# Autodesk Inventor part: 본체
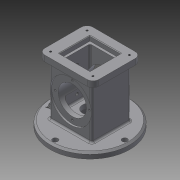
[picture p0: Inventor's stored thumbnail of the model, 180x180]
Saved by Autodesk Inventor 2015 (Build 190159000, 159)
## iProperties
Created: 2019-08
Part Number: 본체
Material: 일반
Document SubType Name: Modeling
Designer: now
Density: 1 g/cm^3
Appearance: 기본값
Author: now
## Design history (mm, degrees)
sketch "스케치1"
  geometry: C1 r 67.5 at (0, 0); 1 further point
  constraints: 1 centre point, 1 coincident
  dimensions: "d0" = 135 diameter of C1
extrude "돌출1" new body sketch "스케치1" distance "d1" = 10; taper "d2" = 0 deg
sketch "스케치2"
  geometry: L1 (-36, 33)-(36, 33); L2 (36, 33)-(36, -33); L3 (36, -33)-(-36, -33); L4 (-36, -33)-(-36, 33); L5 (-36, 33)-(36, -33); L6 (36, 33)-(-36, -33); C1 r 67.5 at (0, 0) reference
  constraints: 12 end point, 2 midpoint, 2 parallel, 1 horizontal, 1 perpendicular
  dimensions: "d3" = 72 distance of L1.start L1.end; "d4" = 66 distance of L3.end L1.start
extrude "돌출2" join sketch "스케치2" distance "d5" = 98; taper "d6" = 0 deg
sketch "스케치4"
  geometry: L1 (-31.5, -10)-(103.5, -10) reference; C1 r 35 at (36, 44); 2 further points
  constraints: 1 centre point, 1 midpoint, 1 vertical alignment
  dimensions: "d8" = 70 diameter of C1; "d9" = 54 distance from line of L1 C1.centre
extrude "돌출3" cut sketch "스케치4" distance "d10" = 3; taper "d11" = 0 deg
sketch "스케치5"
  geometry: C1 r 35 at (0, 0) reference; 1 further point
hole "구멍1" sketch "스케치5" at (0, 0) diameter "d12" = 48; stored, may be unused: countersink angle "d16" = 90 deg, drill point angle "d18" = 118 deg; dims "d13" = 6, "d14" = 4, "d15" = 2, "d17" = 8
fillet "모깎기1" dims "d19" = 3
fillet "모깎기2" dims "d20" = 3
sketch "스케치6"
  geometry: L1 (-46, 41)-(46, 41); L2 (46, 41)-(46, -41); L3 (46, -41)-(-46, -41); L4 (-46, -41)-(-46, 41); L5 (-46, 41)-(46, -41); L6 (46, 41)-(-46, -41); 1 further point
  constraints: 12 end point, 2 midpoint, 2 parallel, 1 horizontal, 1 perpendicular
  dimensions: "d21" = 82 distance of L1.end L2.end; "d22" = 92 distance of L1.start L1.end
extrude "돌출4" join sketch "스케치6" distance "d23" = 10; taper "d24" = 0 deg
fillet "모깎기3" dims "d25" = 10
node "작업 평면2"
sketch "스케치9"
  geometry: 13 further points
  constraints: 4 other
hole "구멍2" sketch "스케치9" at (-36, 31), (-36, -31), (36, -31), (36, 31) diameter "d38" = 3.242; stored, may be unused: countersink angle "d42" = 90 deg, drill point angle "d44" = 118 deg; dims "d39" = 4, "d40" = 4, "d41" = 2, "d43" = 6
sketch "스케치10"
  geometry: C1 r 24 at (0, 0) reference; 2 further points
  constraints: 1 vertical alignment
  dimensions: "d45" = 29 distance of C1.centre point (0, 29)
hole "구멍3" sketch "스케치10" at (0, 29) diameter "d46" = 3.242; stored, may be unused: countersink angle "d50" = 90 deg, drill point angle "d52" = 118 deg; dims "d47" = 4, "d48" = 4, "d49" = 2, "d51" = 6
chamfer "모따기2" distance "d56" = 3; stored, may be unused: second distance "d57" = 2, angle "d58" = 45 deg
sketch "스케치14"
  geometry: C1 r 67.5 at (0, 0) reference; C2 r 25 at (0, 0)
  constraints: 1 centre point, 1 coincident
  dimensions: "d74" = 50 diameter of C2
extrude "돌출9" cut sketch "스케치14" distance "d75" = 18; taper "d76" = 0 deg
fillet "모깎기5" dims "d84" = 3
sketch "스케치17" dims "d96" = 118
  geometry: C1 r 64.5 at (0, 0) reference; 2 further points
  constraints: 2 vertical alignment, 1 coincident, 2 other
hole "구멍7" sketch "스케치17" at (0, 59) diameter "d97" = 9; stored, may be unused: countersink angle "d101" = 90 deg, drill point angle "d103" = 118 deg; dims "d98" = 50, "d99" = 4, "d100" = 2, "d102" = 59.3
sketch "스케치18"
  geometry: C1 r 64.5 at (0, 0) reference; A1 r 59 centre (0, 0) between (0, -59) and (59, 0)
  constraints: 2 point on circle, 1 centre point, 1 coincident, 1 horizontal alignment, 1 vertical alignment
  dimensions: "d107" = 118 diameter of A1
hole "구멍8" sketch "스케치18" at (0, -59), (59, 0) diameter "d108" = 9; stored, may be unused: countersink angle "d112" = 90 deg, drill point angle "d114" = 118 deg; dims "d109" = 50, "d110" = 4, "d111" = 2, "d113" = 59.3
sketch "스케치19"
  geometry: C1 r 64.5 at (0, 0) reference; C2 r 59 at (0, 0)
  constraints: 1 centre point, 1 coincident, 1 other
  dimensions: "d115" = 118 diameter of C2
feature "엠보싱1" sketch "스케치19" dims "d116" = 0.5, "d117" = 0
sketch "스케치20"
  geometry: L1 (-13, 97.5)-(-13, -37.5) reference; 3 further points
  constraints: 2 horizontal alignment
  dimensions: "d132" = 37 distance from line of point (24, 30) L1; "d133" = 43 distance of point (67, 30) point (24, 30)
hole "구멍9" sketch "스케치20" at (67, 30), (24, 30) diameter "d120" = 4.917; stored, may be unused: countersink angle "d124" = 90 deg, drill point angle "d126" = 118 deg; dims "d121" = 12, "d122" = 4, "d123" = 2, "d125" = 35
sketch "스케치21"
  geometry: C1 r 22 at (0, 0) reference; C2 r 12.5 at (0, 0)
  constraints: 1 centre point, 1 coincident
  dimensions: "d129" = 25 diameter of C2
extrude "돌출10" cut sketch "스케치21" stored distance "d130" = 10; taper "d131" = 0 deg
sketch "스케치22"
  geometry: L1 (-22, -22)-(-22, 22) reference; L2 (-22, 22)-(19, 22) reference; L3 (22, 19)-(22, -22) reference; L4 (22, -22)-(-22, -22) reference; L5 (-26, -26)-(26, -26); L6 (26, -26)-(26, 26); L7 (26, 26)-(-26, 26); L8 (-26, 26)-(-26, -26); L9 (-26, -26)-(26, 26); L10 (26, -26)-(-26, 26); A1 r 3 centre (19, 19) between (22, 19) and (19, 22) reference; 1 further point
  constraints: 12 end point, 2 midpoint, 2 parallel, 1 horizontal, 1 perpendicular
  dimensions: "d134" = 52 distance of L6.end L7.end; "d135" = 52 distance between parallel lines of L5 L7
extrude "돌출11" cut sketch "스케치22" distance "d136" = 8; taper "d137" = 0 deg
node "작업 평면1"
chamfer "모따기3" distance "d152" = 1; stored, may be unused: second distance "d153" = 2, angle "d154" = 45 deg
sketch "스케치26"
  geometry: L1 (-26, -26)-(26, -26); L2 (26, -26)-(26, 26); L3 (26, 26)-(-26, 26); L4 (-26, 26)-(-26, -26); L5 (-26, -26)-(26, 26); L6 (26, -26)-(-26, 26); 1 further point
  constraints: 12 end point, 2 midpoint, 2 parallel, 1 horizontal, 1 perpendicular
  dimensions: "d155" = 52 distance of L3.end L1.start; "d156" = 52 distance between parallel lines of L4 L2
extrude "돌출13" cut sketch "스케치26" distance "d157" = 8; taper "d158" = 0 deg
sketch "스케치27"
  geometry: L1 (-22, -22)-(22, -22); L2 (22, -22)-(22, 22); L3 (22, 22)-(-22, 22); L4 (-22, 22)-(-22, -22); L5 (-22, -22)-(22, 22); L6 (22, -22)-(-22, 22); C1 r 12.5 at (0, 0) reference
  constraints: 12 end point, 2 midpoint, 2 parallel, 1 horizontal, 1 perpendicular
  dimensions: "d159" = 44 distance of L2.end L3.end; "d160" = 44 distance of L3.end L1.start
extrude "돌출14" cut sketch "스케치27" distance "d161" = 74; taper "d162" = 0 deg
fillet "모깎기11" dims "d163" = 3
fillet "모깎기12" dims "d164" = 3
fillet "모깎기13" dims "d165" = 3
sketch "스케치28"
  geometry: A1 r 10 centre (36, 31) between (46, 31) and (36, 41) reference; A2 r 10 centre (-36, 31) between (-36, 41) and (-46, 31) reference; A3 r 10 centre (-36, -31) between (-46, -31) and (-36, -41) reference; A4 r 10 centre (36, -31) between (36, -41) and (46, -31) reference; 1 further point
hole "구멍11" sketch "스케치28" at (36, -31), (-36, 31), (36, 31), (-36, -31) diameter "d166" = 3.242; stored, may be unused: countersink angle "d170" = 90 deg, drill point angle "d172" = 118 deg; dims "d167" = 4, "d168" = 4, "d169" = 2, "d171" = 6
node "솔리드1"
pattern_circular "원형 패턴1" dims angle "d54" = 360 deg
mirror "대칭1"
